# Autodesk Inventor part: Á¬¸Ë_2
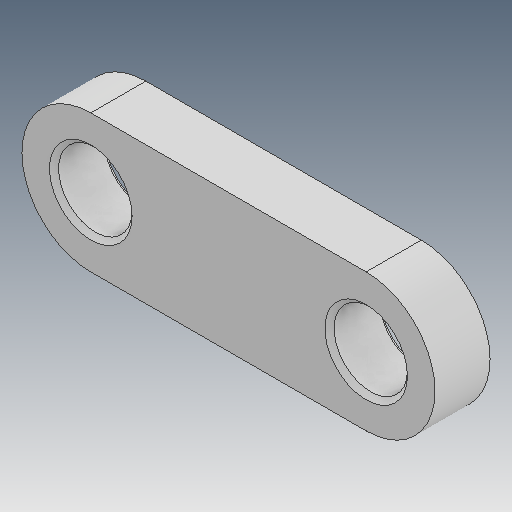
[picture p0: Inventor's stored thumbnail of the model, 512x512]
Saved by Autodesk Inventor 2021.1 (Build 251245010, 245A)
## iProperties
Created: 2019-04
Part Number: Á¬¸Ë_2
Material: Ogólny
Document SubType Name: Modeling
Designer: user
Density: 1 g/cm^3
Appearance: Domyślna
Author: user
Revision Number: ÈÎºÎ
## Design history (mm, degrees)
feature "ÊäÈë1"
node "Bryła1"
